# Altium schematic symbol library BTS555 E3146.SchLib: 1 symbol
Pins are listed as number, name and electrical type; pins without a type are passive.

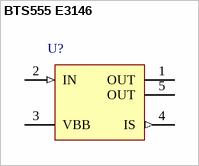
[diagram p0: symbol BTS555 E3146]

## BTS555 E3146
designator U?
Smart High-Side High Current Power Switch, 1 Channel, 45 A Load Current, -40 to 150 degC, P-TO218-5-146, Reel, Green; Manufacturer: Infineon; PartNumber: BTS555 E3146; Channels: 1; Green: TRUE; Group: Automotive Qualified; Load Current (typ): 45 A; Ptot (max): 360 W; Recommended Operating Voltage Max.: 34 V; Recommended Operating Voltage Min.: 5 V; RON @ 25degreesC: 2.5 mOhm; RON(max) @ 150degreesC: 4 mOhm; toff (max): 200 us; ton (max): 600 us
footprint INF-P-TO218-5-146 (FM, 5-Leads, Body 15x12.5mm, Pitch 2.54mm)
pins: 1 OUT (power) "Output to the load. The pins1 and 5 must be shorted with each other especially in high current applications!", 2 IN (in) "Input, activates the power switch in case of short to ground", 3 VBB (power) "Positive power supply voltage, the tab is electrically connected to this pin.In high current applications the tab should be used for the Vbb connection instead of this pin", 4 IS (out) "Diagnostic feedback providing a sense current proportional to the load current; zero current on failure (see Truth Table on page 7)", 5 OUT (power) "Output to the load. The pins1 and 5 must be shorted with each other especially in high current applications!"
